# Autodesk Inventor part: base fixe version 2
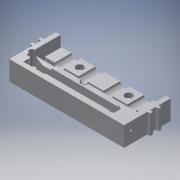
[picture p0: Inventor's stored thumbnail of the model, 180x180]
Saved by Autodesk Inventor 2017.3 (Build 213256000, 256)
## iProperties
Part Number: base fixe version 2
Material: Plastique ABS
Document SubType Name: Modeling
Designer: ficho
Density: 1.06 g/cm^3
Appearance: Lisse - Blanc
Mass: 70.6115 g
Surface Area: 265.121 cm^2
Volume: 66.6147 cm^3
Author: ficho
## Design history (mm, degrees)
sketch "Esquisse1"
  geometry: L1 (0, 0)-(123, 0); L2 (123, 0)-(123, 50); L3 (123, 50)-(0, 50); L4 (0, 50)-(0, 0); L5 (10, 27)-(32, 27); L6 (32, 27)-(32, 5); L7 (32, 5)-(10, 5); L8 (10, 5)-(10, 27); L9 (64, 22.377)-(115.5, 22.377); L10 (115.5, 22.377)-(115.5, 19.177); L11 (115.5, 19.177)-(64, 19.177); L12 (64, 19.177)-(64, 22.377); L13 (59, 19.177)-(7.5, 19.177); L14 (7.5, 19.177)-(7.5, 22.377); L15 (7.5, 22.377)-(59, 22.377); L16 (59, 22.377)-(59, 19.177); C1 r 6 at (103, 10); C2 r 4 at (21, 10)
  constraints: 32 end point, 8 parallel, 4 horizontal, 4 perpendicular, 2 centre point, 2 point on line
  dimensions: "d0" = 123 distance between parallel lines of L2 L4; "d1" = 50 distance between parallel lines of L3 L1; "d2" = 22 distance of L6.end L7.end; "d3" = 22 distance of L5.end L6.end; "d4" = 12 diameter of C1; "d5" = 10 distance from line of C1.centre L1; "d6" = 20 distance from line of L2 C1.centre; "d7" = 5 distance between parallel lines of L1 L7; "d8" = 10 distance between parallel lines of L8 L4; "d9" = 51.5 distance of L10.end L11.end; "d10" = 3.2 distance of L9.end L10.end; "d11" = 51.5 distance of L14.end L15.end; "d12" = 5 distance between parallel lines of L12 L16; "d13" = 7.5 distance between parallel lines of L4 L14; "d14" = 7.5 distance between parallel lines of L2 L10 (derived); "d21" = 8 diameter of C2
extrude "Extrusion1" new body sketch "Esquisse1" distance "d15" = 5; taper "d16" = 0 deg
sketch "Esquisse2"
  geometry: L1 (0, 50)-(5, 50); L2 (5, 50)-(5, 22.177); L3 (5, 0)-(0, 0); L4 (0, 0)-(0, 50); L5 (123, 50)-(118, 50); L6 (118, 50)-(118, 19.177); L7 (118, 0)-(123, 0); L8 (123, 0)-(123, 50); L9 (59, 19.177)-(7.5, 19.177) reference; L10 (118, 0)-(5, 0); L11 (10.743, 19.177)-(57.5, 19.177); L12 (65.5, 19.177)-(118, 19.177); L13 (106.005, 13.962)-(106.005, 5.962); L14 (18.825, 6.643)-(3.369, 16.659); L15 (21.831, 13.962)-(10.567, 18.209); L16 (102.4, 15.2)-(103.6, 15.2); L17 (103.6, 4.8)-(102.4, 4.8); L18 (103.6, 13.962)-(106.005, 13.962); L19 (102.4, 4.8)-(102.4, 5.962); L20 (102.4, 13.962)-(102.4, 15.2); L21 (103.6, 15.2)-(103.6, 13.962); L22 (103.6, 5.962)-(103.6, 4.8); L23 (106.005, 5.962)-(103.6, 5.962); L24 (0, 50)-(0, 0); L25 (102.4, 5.962)-(20.998, 6); L26 (21.831, 13.962)-(102.4, 13.962); A1 r 4 centre (61.5, 19.177) between (57.5, 19.177) and (65.5, 19.177); A2 r 3 centre (5, 19.177) between (5, 22.177) and (3.369, 16.659); A3 r 4 centre (21, 10) between (18.825, 6.643) and (20.998, 6) reference; A4 r 4 centre (21, 10) between (18.825, 6.643) and (20.998, 6); A5 r 0.5 centre (10.743, 18.677) between (10.743, 19.177) and (10.567, 18.209); 2 further points
  constraints: 50 end point, 12 parallel, 11 point on circle, 7 horizontal, 6 perpendicular, 6 tangent, 5 point on line, 4 centre point, 1 coincident, 1 vertical
  dimensions: "d17" = 5 distance of L3.end L3.start; "d18" = 5 distance of L7.end L7.start; "d19" = 8 diameter of A1; "d23" = 8 distance of L13.start L13.end; "d24" = 6 diameter of A2; "d27" = 5.2 distance from line of point (103, 10) L16; "d28" = 10.4 distance between parallel lines of L17 L16 (= 2 x d27); "d29" = 0.5 radius of A5
extrude "Extrusion2" join sketch "Esquisse2" distance "d30" = 5; taper "d31" = 0 deg
sketch "Esquisse3"
  geometry: L1 (0, 50)-(0, 0) reference; L2 (0, 0)-(123, 0) reference; L3 (123, 0)-(123, 50) reference; L4 (123, 50)-(118, 50) reference; L5 (118, 50)-(118, 19.177) reference; L6 (118, 19.177)-(65.5, 19.177) reference; L7 (57.5, 19.177)-(10.743, 19.177) reference; L8 (10.567, 18.209)-(21.831, 13.962) reference; L9 (21.831, 13.962)-(102.4, 13.962) reference; L10 (102.4, 13.962)-(102.4, 15.2) reference; L11 (102.4, 15.2)-(103.6, 15.2) reference; L12 (103.6, 15.2)-(103.6, 13.962) reference; L13 (103.6, 13.962)-(106.005, 13.962) reference; L14 (106.005, 13.962)-(106.005, 5.962) reference; L15 (106.005, 5.962)-(103.6, 5.962) reference; L16 (103.6, 5.962)-(103.6, 4.8) reference; L17 (103.6, 4.8)-(102.4, 4.8) reference; L18 (102.4, 4.8)-(102.4, 5.962) reference; L19 (102.4, 5.962)-(20.998, 6) reference; L20 (18.825, 6.643)-(3.369, 16.659) reference; L21 (5, 22.177)-(5, 50) reference; L22 (5, 50)-(0, 50) reference; A1 r 4 centre (61.5, 19.177) between (57.5, 19.177) and (65.5, 19.177) reference; A2 r 0.5 centre (10.743, 18.677) between (10.743, 19.177) and (10.567, 18.209) reference; A3 r 4 centre (21, 10) between (20.998, 6) and (18.825, 6.643) reference; A4 r 3 centre (5, 19.177) between (5, 22.177) and (3.369, 16.659) reference; 2 further points
  constraints: 1 coincident, 3 other
extrude "Extrusion3" cut sketch "Esquisse3" stored distance "d32" = 5; taper "d33" = 0 deg
sketch "Esquisse4"
  geometry: L1 (5, 22.177)-(5, 50) reference; L2 (5, 50)-(0, 50) reference; L3 (0, 50)-(0, 0) reference; L4 (0, 0)-(123, 0) reference; L5 (123, 0)-(123, 50) reference; L6 (123, 50)-(118, 50) reference; L7 (118, 50)-(118, 19.177) reference; L8 (118, 19.177)-(65.5, 19.177) reference; L9 (57.5, 19.177)-(10.743, 19.177) reference; L10 (10.567, 18.209)-(21.831, 13.962) reference; L11 (102.4, 13.962)-(102.4, 15.2) reference; L12 (102.4, 15.2)-(103.6, 15.2) reference; L13 (103.6, 15.2)-(103.6, 13.962) reference; L14 (103.6, 13.962)-(106.005, 13.962) reference; L15 (106.005, 13.962)-(106.005, 5.962) reference; L16 (106.005, 5.962)-(103.6, 5.962) reference; L17 (103.6, 5.962)-(103.6, 4.8) reference; L18 (103.6, 4.8)-(102.4, 4.8) reference; L19 (102.4, 4.8)-(102.4, 5.962) reference; L20 (102.4, 5.962)-(20.998, 6) reference; L21 (21.831, 13.962)-(102.4, 13.962) reference; L22 (18.825, 6.643)-(3.369, 16.659) reference; L23 (5, 22.177)-(5, 50) reference; L24 (5, 50)-(0, 50) reference; L25 (0, 50)-(0, 0) reference; L26 (0, 0)-(123, 0) reference; L27 (123, 0)-(123, 50) reference; L28 (123, 50)-(118, 50) reference; L29 (118, 50)-(118, 19.177) reference; L30 (118, 19.177)-(65.5, 19.177) reference; L31 (57.5, 19.177)-(10.743, 19.177) reference; L32 (10.567, 18.209)-(21.831, 13.962) reference; L33 (21.831, 13.962)-(102.4, 13.962) reference; L34 (102.4, 13.962)-(102.4, 15.2) reference; L35 (102.4, 15.2)-(103.6, 15.2) reference; L36 (103.6, 15.2)-(103.6, 13.962) reference; L37 (103.6, 13.962)-(106.005, 13.962) reference; L38 (106.005, 13.962)-(106.005, 5.962) reference; L39 (106.005, 5.962)-(103.6, 5.962) reference; L40 (103.6, 5.962)-(103.6, 4.8) reference; L41 (103.6, 4.8)-(102.4, 4.8) reference; L42 (102.4, 4.8)-(102.4, 5.962) reference; L43 (102.4, 5.962)-(20.998, 6) reference; A1 r 4 centre (61.5, 19.177) between (57.5, 19.177) and (65.5, 19.177) reference; A2 r 0.5 centre (10.743, 18.677) between (10.743, 19.177) and (10.567, 18.209) reference; A3 r 4 centre (21, 10) between (18.825, 6.643) and (20.998, 6) reference; A4 r 3 centre (5, 19.177) between (5, 22.177) and (3.369, 16.659) reference; A5 r 4 centre (61.5, 19.177) between (57.5, 19.177) and (65.5, 19.177) reference; A6 r 0.5 centre (10.743, 18.677) between (10.743, 19.177) and (10.567, 18.209) reference
extrude "Extrusion4" join sketch "Esquisse4" distance "d34" = 11; taper "d35" = 0 deg
sketch "Esquisse5"
  geometry: L1 (10, 5)-(10, 27) reference; L2 (10, 27)-(32, 27) reference; L3 (32, 27)-(32, 5) reference; L4 (32, 5)-(10, 5); L5 (10, 5)-(10, 14.22); L6 (32, 10.36)-(32, 5); L7 (10, 14.22)-(32, 10.36); 1 further point
  constraints: 8 end point, 1 horizontal, 1 perpendicular
extrude "Extrusion5" cut sketch "Esquisse5" distance "d36" = 16; taper "d37" = 0 deg
fillet "Congé1" dims "d38" = 2
sketch "Esquisse6"
  geometry: L1 (0, 37)-(-3, 37); L2 (-3, 37)-(-3, 34); L3 (-3, 34)-(0, 34); L4 (0, 34)-(0, 37); L5 (0, 50)-(0, 0) reference; L6 (0, 28)-(-3, 28); L7 (-3, 28)-(-3, 25); L8 (-3, 25)-(0, 25); L9 (0, 25)-(0, 28); L10 (159.922, 37)-(163.822, 37); L11 (163.822, 37)-(163.822, 34); L12 (163.822, 34)-(159.922, 34); L13 (159.922, 34)-(159.922, 37); L14 (0, 0)-(123, 0) reference; L15 (123, 0)-(123, 50) reference; L16 (123, 37)-(126, 37); L17 (126, 37)-(126, 34); L18 (126, 34)-(123, 34); L19 (123, 34)-(123, 37); L20 (123, 28)-(126, 28); L21 (126, 28)-(126, 25); L22 (126, 25)-(123, 25); L23 (123, 25)-(123, 28)
  constraints: 40 end point, 10 parallel, 6 point on line, 5 horizontal, 5 perpendicular
  dimensions: "d40" = 3 distance between parallel lines of L2 L4; "d41" = 25 distance between parallel lines of L8 L14; "d42" = 3 distance between parallel lines of L8 L6; "d43" = 3 distance between parallel lines of L5 L7; "d44" = 6 distance between parallel lines of L6 L3; "d45" = 3 distance between parallel lines of L3 L1; "d46" = 3 distance of L17.end L18.end; "d47" = 3 distance of L16.end L17.end; "d48" = 3 distance of L21.end L22.end; "d49" = 3 distance of L20.end L21.end; "d50" = 25 distance between parallel lines of L22 L14 (= d41); "d51" = 6 distance between parallel lines of L18 L20 (= d44)
extrude "Extrusion6" join sketch "Esquisse6" distance "d52" = 21; taper "d53" = 0 deg
sketch "Esquisse8"
  geometry: L1 (-5.743, 0)-(-5.743, -16) reference; L2 (20.478, -16)-(-5.743, -16); L3 (-5.743, -16)-(-5.743, -14); L4 (-5.743, -14)-(20.478, -14); L5 (20.478, -14)-(20.478, -16); 1 further point
  constraints: 8 end point, 2 parallel, 1 horizontal, 1 perpendicular, 1 point on line
  dimensions: "d54" = 2 distance between parallel lines of L2 L4
extrude "Extrusion7" cut sketch "Esquisse8" distance "d55" = 6; taper "d56" = 0 deg
sketch "Esquisse10"
  geometry: C1 r 1.25 at (10.928, -5.854) reference; C2 r 1.25 at (36.428, -5.854) reference; C3 r 1.25 at (63.274, -5.854) reference; C4 r 1.25 at (88.774, -5.854) reference; 1 further point
hole "Perçage1" sketch "Esquisse10" at (10.928, -5.854), (63.274, -5.854), (36.428, -5.854), (88.774, -5.854) diameter "d57" = 1.5; stored, may be unused: countersink angle "d61" = 90 deg, drill point angle "d63" = 118 deg; dims "d58" = 6, "d59" = 4, "d60" = 2, "d62" = 5
sketch "Esquisse11"
  geometry: C1 r 1.5 at (12.5, 7.5) reference; 1 further point
hole "Perçage2" sketch "Esquisse11" at (12.5, 7.5) diameter "d64" = 2; stored, may be unused: countersink angle "d68" = 90 deg, drill point angle "d70" = 118 deg; dims "d65" = 6, "d66" = 4, "d67" = 2, "d69" = 5
sketch "Esquisse12"
  geometry: C1 r 1.5 at (8.5, 7.5) reference; 1 further point
hole "Perçage3" sketch "Esquisse12" at (8.5, 7.5) diameter "d71" = 2; stored, may be unused: countersink angle "d75" = 90 deg, drill point angle "d77" = 118 deg; dims "d72" = 6, "d73" = 4, "d74" = 2, "d76" = 5
sketch "Esquisse13"
  geometry: L1 (117, 52)-(117, 30.5) reference; L2 (6, 30.5)-(6, 52) reference; L3 (118, 50)-(5, 50) reference; L4 (6, 50)-(117, 50); L5 (117, 50)-(117, 32); L6 (117, 32)-(6, 32); L7 (6, 32)-(6, 50); 1 further point
  constraints: 12 end point, 3 point on line, 2 parallel, 2 vertical, 1 horizontal, 1 perpendicular, 4 other
  dimensions: "d78" = 18 distance of L4.end L5.end
extrude "Extrusion8" join sketch "Esquisse13" distance "d79" = 5; taper "d80" = 0 deg
sketch "Esquisse14"
  geometry: C1 r 0.75 at (21.671, -10.854) reference; C2 r 0.75 at (47.171, -10.854) reference; C3 r 0.75 at (74.017, -10.854) reference; C4 r 1.25 at (99.517, -10.854) reference; C5 r 5 at (21.671, -10.854); C6 r 5 at (47.171, -10.854); C7 r 5 at (74.017, -10.854); C8 r 5 at (99.517, -10.854); 1 further point
  constraints: 5 centre point, 4 coincident, 2 other
  dimensions: "d81" = 10 diameter of C5; "d82" = 10 diameter of C6; "d83" = 10 diameter of C7; "d84" = 10 diameter of C8
extrude "Extrusion9" cut sketch "Esquisse14" stored distance "d85" = 5; taper "d86" = 0 deg
sketch "Esquisse15"
  geometry: L1 (42.245, 32)-(42.245, 50) reference; L2 (26.598, 50)-(26.598, 32) reference; L3 (78.943, 50)-(78.943, 32) reference; L4 (94.59, 32)-(94.59, 50) reference; L5 (42.245, 50)-(26.598, 32); L6 (94.59, 50)-(78.943, 32); 3 further points
  constraints: 4 end point, 2 midpoint, 1 parallel
hole "Perçage4" sketch "Esquisse15" at (34.421, 41), (86.767, 41) diameter "d87" = 5; stored, may be unused: countersink angle "d91" = 90 deg, drill point angle "d93" = 118 deg; dims "d88" = 6, "d89" = 8, "d90" = 5, "d92" = 8
node "Solide1"
node "Boucle projetée1"
node "Boucle projetée2"
node "Référence2"
node "Référence3"
node "Référence4"
node "Référence5"
node "Référence6"
node "Référence7"
other parameters: "d25" = 1.2 (= 2 x d26), "d26" = 0.6
